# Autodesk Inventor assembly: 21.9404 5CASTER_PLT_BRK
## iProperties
Created: 2010-10
Part Number: 21.9404 5CASTER_PLT_BRK
Document SubType Name: Assembly
Designer: Administrator
Translation Standard: STEP AP214IS
FileName: Colson-2.03256.445 BRK5 .step.step
PreProcessor: SolidWorks 2010
PostProcessor: Build: 236a, Release: 2009 RTM - Date: Fri 02/22/2008
Sent Units: Inches
Uncertainty: 1e-05
Author: Administrator
